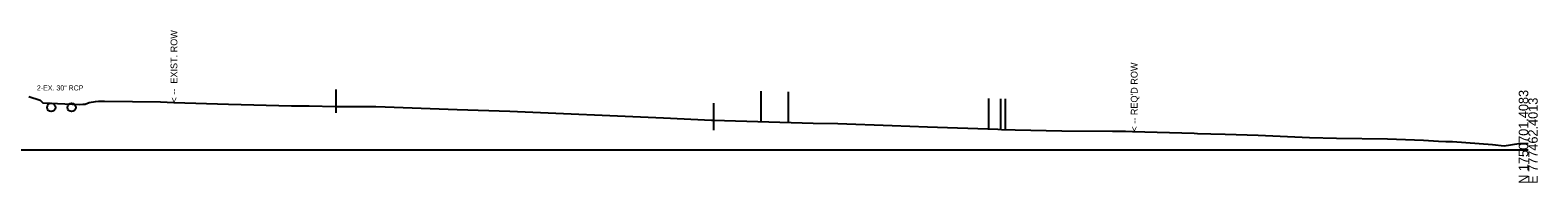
# Model space of a CAD drawing. Extents: x 776426 to 854588, y 1736205 to 1756790.
# Drawn here: x 805228.4 to 805673.6, y 1754705.1 to 1754750.1 of the extents above; entities that cross this region are included whole.
import ezdxf

# ---------------------------------------------------------------- set-up
doc = ezdxf.new("R2010")
doc.units = 0
for name, color, linetype in [('DTM CONTOURS_MAJOR_TX', 7, 'Continuous'), ('DTM_X_FLOW_ARROWS', 7, 'Continuous'), ('TRANS_CURB_GUTTER', 7, 'Continuous'), ('TRANS_EOP_PAVED', 7, 'Continuous'), ('TRANS_UNPAVED_SHOULDERS', 7, 'Continuous'), ('X_TRANS_EOP', 7, 'Continuous'), ('XS_P_ROW', 7, 'Continuous'), ('XS_X_DRAINAGE', 7, 'Continuous'), ('XS_X_ROW', 7, 'Continuous'), ('XS_X_TX', 7, 'Continuous')]:
    doc.layers.add(name, color=color, linetype=linetype)

msp = doc.modelspace()

# ---------------------------------------------------------------- linework, layer by layer
at = {"layer": 'DTM CONTOURS_MAJOR_TX'}
msp.add_line((805170.79, 1754714.76), (805670.79, 1754714.76), dxfattribs=at)
at = {"layer": 'DTM_X_FLOW_ARROWS'}
msp.add_lwpolyline([(805227.94, 1754730.5), (805231.36, 1754729.39), (805232.08, 1754728.62), (805242.93, 1754728.15), (805243.91, 1754728.23), (805244.63, 1754728.28), (805245.78, 1754728.75), (805247.71, 1754729.07), (805248.5, 1754729.09), (805249.57, 1754729.09), (805250.35, 1754729.11), (805266.89, 1754728.89), (805270.75, 1754728.74), (805286.92, 1754728.24), (805305.52, 1754727.79), (805310.73, 1754727.77), (805318.59, 1754727.56), (805330.48, 1754727.52), (805333.25, 1754727.48), (805354.52, 1754726.7), (805370.04, 1754726.21), (805415.39, 1754724.18), (805429.59, 1754723.52), (805430.15, 1754723.5), (805459.62, 1754722.65), (805466.92, 1754722.54), (805482.95, 1754721.91), (805493.35, 1754721.54), (805514.13, 1754720.84), (805515.2, 1754720.82), (805519.26, 1754720.72), (805533.03, 1754720.42), (805548, 1754720.29), (805550.4, 1754720.3), (805551.86, 1754720.27), (805553.9, 1754720.2), (805572.16, 1754719.65), (805573.08, 1754719.62), (805577.04, 1754719.47), (805581.26, 1754719.42), (805591.01, 1754719.14), (805606.23, 1754718.41), (805614.18, 1754718.18), (805629.18, 1754718.05), (805639.9, 1754717.65), (805644.32, 1754717.32), (805646.43, 1754717.29), (805648.45, 1754717.22), (805660.21, 1754716.4), (805663.69, 1754715.95), (805668.02, 1754716.61), (805670.79, 1754716.68)], dxfattribs=at)
at = {"layer": 'TRANS_CURB_GUTTER'}
for p, q in [((805514.96, 1754729.82), (805514.96, 1754720.82)), ((805514.96, 1754729.82), (805514.96, 1754720.82)), ((805516.36, 1754729.79), (805516.36, 1754720.79)), ((805516.36, 1754729.79), (805516.36, 1754720.79))]:
    msp.add_line(p, q, dxfattribs=at)
at = {"layer": 'TRANS_EOP_PAVED'}
for p, q in [((805452.21, 1754731.86), (805452.21, 1754722.86)), ((805452.21, 1754731.86), (805452.21, 1754722.86)), ((805511.38, 1754729.93), (805511.38, 1754720.93)), ((805511.38, 1754729.93), (805511.38, 1754720.93))]:
    msp.add_line(p, q, dxfattribs=at)
at = {"layer": 'TRANS_UNPAVED_SHOULDERS'}
msp.add_line((805444.2, 1754732.1), (805444.2, 1754723.1), dxfattribs=at)
msp.add_line((805444.2, 1754732.1), (805444.2, 1754723.1), dxfattribs=at)
at = {"layer": 'X_TRANS_EOP'}
for p, q in [((805318.6, 1754732.56), (805318.6, 1754727.56)), ((805318.6, 1754732.56), (805318.6, 1754727.56)), ((805318.6, 1754730.72), (805318.6, 1754725.72)), ((805430.16, 1754728.5), (805430.16, 1754723.5)), ((805430.16, 1754728.5), (805430.16, 1754723.5)), ((805430.16, 1754725.55), (805430.16, 1754720.55))]:
    msp.add_line(p, q, dxfattribs=at)
at = {"layer": 'XS_X_DRAINAGE'}
for centre in [(805234.61, 1754727.3), (805240.62, 1754727.3)]:
    msp.add_circle(centre, 1.25, dxfattribs=at)

# ---------------------------------------------------------------- texts
at = {"layer": 'DTM CONTOURS_MAJOR_TX'}
for s, p in [('N 1750701.4083', (805670.79, 1754704.76)), ('E 777462.4013', (805673.59, 1754704.76))]:
    msp.add_text(s, height=2.8, rotation=90, dxfattribs=at).set_placement(p)
at = {"layer": 'XS_P_ROW'}
msp.add_text("< -- REQ'D ROW", height=2, rotation=90, dxfattribs=at).set_placement((805555.42, 1754720.18))
at = {"layer": 'XS_X_ROW'}
msp.add_text('< --  EXIST. ROW', height=2, rotation=90, dxfattribs=at).set_placement((805271.83, 1754728.74))
at = {"layer": 'XS_X_TX'}
msp.add_text('2-EX. 30" RCP', height=1.5, dxfattribs=at).set_placement((805230.36, 1754732.29))

doc.saveas('drawing.dxf')
